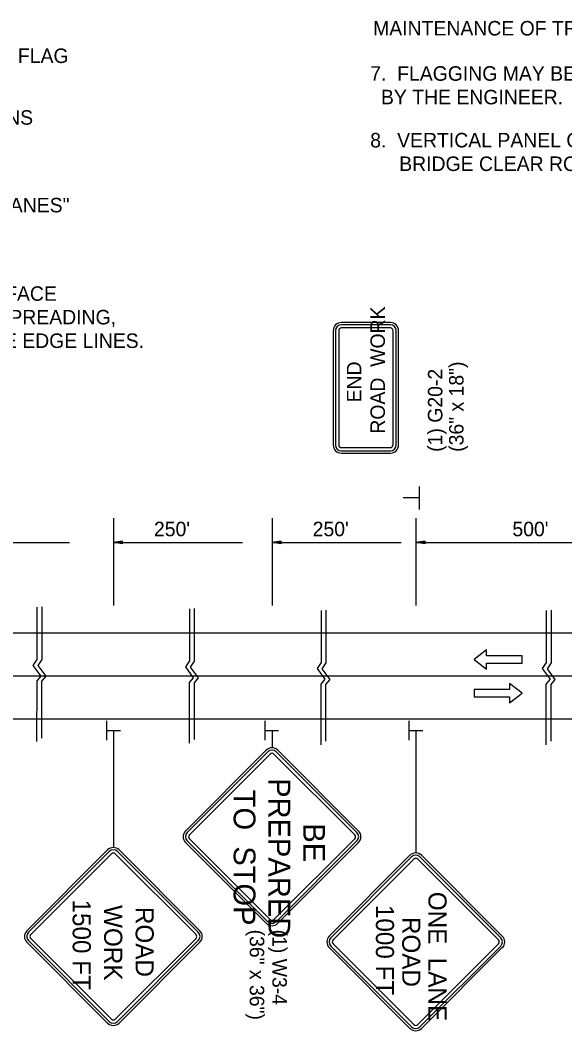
# Model space of a CAD drawing. Extents: x 1926586 to 1930787, y 596452 to 599566.
# Drawn here: x 1928209.4 to 1928434.7, y 597274.9 to 597692.9 of the extents above; entities that cross this region are included whole.
import ezdxf

# ---------------------------------------------------------------- set-up
doc = ezdxf.new("R2010")
doc.units = 0
for name, color, linetype in [('Default', 7, 'Continuous'), ('P_TC_Signs_Permanent', 7, 'Continuous'), ('P_TC_Signs_Temporary', 7, 'Continuous'), ('R_Border', 7, 'Continuous'), ('R_Striping', 7, 'Continuous')]:
    doc.layers.add(name, color=color, linetype=linetype)

msp = doc.modelspace()

# ---------------------------------------------------------------- linework, layer by layer
at = {"layer": 'Default'}
for p, q in [((1928374.44, 597500.09), (1928374.44, 597490.6)), ((1928374.3, 597495.36), (1928367.82, 597495.36)), ((1928247.97, 597486.95), (1928247.97, 597450.92)), ((1928313.63, 597486.95), (1928313.63, 597450.92)), ((1928373.08, 597486.95), (1928373.08, 597450.92)), ((1928176.38, 597476.91), (1928229.78, 597476.93)), ((1928251.81, 597477.5), (1928247.97, 597476.93)), ((1928247.97, 597476.93), (1928301.38, 597476.93)), ((1928251.81, 597476.35), (1928247.97, 597476.93)), ((1928251.81, 597477.41), (1928248.62, 597476.93)), ((1928251.81, 597476.45), (1928248.62, 597476.93)), ((1928251.81, 597477.31), (1928249.28, 597476.93)), ((1928251.81, 597476.55), (1928249.28, 597476.93)), ((1928251.81, 597477.21), (1928249.91, 597476.93)), ((1928251.81, 597476.64), (1928249.91, 597476.93)), ((1928251.81, 597477.12), (1928250.56, 597476.93)), ((1928251.81, 597476.74), (1928250.56, 597476.93)), ((1928251.81, 597477.02), (1928251.21, 597476.93)), ((1928251.81, 597476.84), (1928251.21, 597476.93)), ((1928251.81, 597476.35), (1928251.81, 597477.5)), ((1928317.46, 597477.48), (1928313.63, 597476.91)), ((1928313.63, 597476.91), (1928367.03, 597476.91)), ((1928317.46, 597476.33), (1928313.63, 597476.91)), ((1928317.46, 597477.39), (1928314.27, 597476.91)), ((1928317.46, 597476.43), (1928314.27, 597476.91)), ((1928317.46, 597477.29), (1928314.93, 597476.91)), ((1928317.46, 597476.53), (1928314.93, 597476.91)), ((1928317.46, 597477.19), (1928315.57, 597476.91)), ((1928317.46, 597476.62), (1928315.57, 597476.91)), ((1928317.46, 597477.1), (1928316.22, 597476.91)), ((1928317.46, 597476.72), (1928316.22, 597476.91)), ((1928317.46, 597477), (1928316.86, 597476.91)), ((1928317.46, 597476.82), (1928316.86, 597476.91)), ((1928317.46, 597476.33), (1928317.46, 597477.48)), ((1928376.92, 597477.48), (1928373.08, 597476.91)), ((1928373.08, 597476.91), (1928472.84, 597476.91)), ((1928376.92, 597476.33), (1928373.08, 597476.91)), ((1928376.92, 597477.39), (1928373.72, 597476.91)), ((1928376.92, 597476.43), (1928373.72, 597476.91)), ((1928376.92, 597477.29), (1928374.38, 597476.91)), ((1928376.92, 597476.53), (1928374.38, 597476.91)), ((1928376.92, 597477.19), (1928375.02, 597476.91)), ((1928376.92, 597476.62), (1928375.02, 597476.91)), ((1928376.92, 597477.1), (1928375.67, 597476.91)), ((1928376.92, 597476.72), (1928375.67, 597476.91)), ((1928376.92, 597477), (1928376.31, 597476.91)), ((1928376.92, 597476.82), (1928376.31, 597476.91)), ((1928376.92, 597476.33), (1928376.92, 597477.48)), ((1927870.1, 597439.49), (1929142.12, 597439.49)), ((1927870.1, 597421.7), (1929142.12, 597421.7)), ((1927870.1, 597403.91), (1929142.12, 597403.91)), ((1928245.3, 597395.11), (1928245.3, 597403.12)), ((1928310.78, 597395.11), (1928310.78, 597403.12)), ((1928370.4, 597395.11), (1928370.4, 597403.12)), ((1928245.42, 597399.09), (1928250.88, 597399.09)), ((1928310.9, 597399.09), (1928316.36, 597399.09)), ((1928370.52, 597399.09), (1928375.99, 597399.09))]:
    msp.add_line(p, q, dxfattribs=at)
for points in [[(1928216.38, 597450.1), (1928216.38, 597428.57), (1928214.72, 597426.1), (1928217.96, 597421.67), (1928216.26, 597419.63), (1928216.25, 597394.6)], [(1928218.43, 597450.29), (1928218.43, 597428.49), (1928216.77, 597426.02), (1928220, 597421.59), (1928218.3, 597419.54), (1928218.3, 597396.04)], [(1928279.43, 597449.42), (1928279.43, 597427.9), (1928277.76, 597425.43), (1928281, 597421), (1928279.3, 597418.96), (1928279.29, 597393.93)], [(1928281.47, 597449.62), (1928281.47, 597427.82), (1928279.81, 597425.34), (1928283.05, 597420.92), (1928281.34, 597418.87), (1928281.34, 597395.37)], [(1928333.89, 597448.78), (1928333.89, 597427.26), (1928332.23, 597424.79), (1928335.46, 597420.36), (1928333.76, 597418.31), (1928333.75, 597393.28)], [(1928335.93, 597448.97), (1928335.93, 597427.17), (1928334.27, 597424.7), (1928337.51, 597420.27), (1928335.8, 597418.22), (1928335.8, 597394.72)], [(1928427.05, 597448.78), (1928427.05, 597427.26), (1928425.39, 597424.79), (1928428.63, 597420.36), (1928426.92, 597418.31), (1928426.92, 597393.28)], [(1928429.1, 597448.97), (1928429.1, 597427.17), (1928427.43, 597424.7), (1928430.67, 597420.27), (1928428.97, 597418.22), (1928428.96, 597394.72)]]:
    msp.add_lwpolyline(points, dxfattribs=at)
at = {"layer": 'P_TC_Signs_Permanent'}
for p, q in [((1928311.24, 597391), (1928277.83, 597357.58)), ((1928311.9, 597390.33), (1928278.49, 597356.92)), ((1928312.83, 597389.4), (1928279.42, 597355.99)), ((1928347.83, 597355.99), (1928314.42, 597389.4)), ((1928348.76, 597356.92), (1928315.35, 597390.33)), ((1928349.42, 597357.58), (1928316.01, 597391)), ((1928277.83, 597352.81), (1928311.24, 597319.4)), ((1928278.49, 597353.47), (1928311.9, 597320.06)), ((1928279.42, 597354.4), (1928312.83, 597320.99)), ((1928314.42, 597320.99), (1928347.83, 597354.4)), ((1928315.35, 597320.06), (1928348.76, 597353.47)), ((1928316.01, 597319.4), (1928349.42, 597352.81))]:
    msp.add_line(p, q, dxfattribs=at)
for centre, radius, start, end in [((1928313.63, 597388.61), 3.37, 45, 135), ((1928313.63, 597388.61), 2.44, 45, 135), ((1928313.63, 597388.61), 1.13, 45, 135), ((1928280.22, 597355.2), 3.37, 135, 225), ((1928280.22, 597355.2), 2.44, 135, 225), ((1928280.22, 597355.2), 1.13, 135, 225), ((1928347.04, 597355.2), 1.13, 315, 45), ((1928347.04, 597355.2), 2.44, 315, 45), ((1928347.04, 597355.2), 3.37, 315, 45), ((1928313.63, 597321.79), 3.37, 225, 315), ((1928313.63, 597321.79), 2.44, 225, 315), ((1928313.63, 597321.79), 1.13, 225, 315)]:
    msp.add_arc(centre, radius, start, end, dxfattribs=at)
at = {"layer": 'P_TC_Signs_Temporary'}
for p, q in [((1928338.95, 597564.52), (1928338.95, 597517.27)), ((1928339.88, 597564.52), (1928339.88, 597517.27)), ((1928341.2, 597564.52), (1928341.2, 597517.27)), ((1928362.57, 597567.89), (1928342.32, 597567.89)), ((1928362.57, 597566.96), (1928342.32, 597566.96)), ((1928362.57, 597565.64), (1928342.32, 597565.64)), ((1928363.7, 597517.27), (1928363.7, 597564.52)), ((1928365.01, 597517.27), (1928365.01, 597564.52)), ((1928365.95, 597517.27), (1928365.95, 597564.52)), ((1928342.32, 597516.14), (1928362.57, 597516.14)), ((1928342.32, 597514.83), (1928362.57, 597514.83)), ((1928342.32, 597513.89), (1928362.57, 597513.89)), ((1928212.18, 597316.34), (1928245.59, 597349.75)), ((1928212.84, 597315.68), (1928246.25, 597349.09)), ((1928213.77, 597314.75), (1928247.18, 597348.16)), ((1928248.77, 597348.16), (1928282.18, 597314.75)), ((1928249.7, 597349.09), (1928283.11, 597315.68)), ((1928250.36, 597349.75), (1928283.77, 597316.34)), ((1928337.28, 597314.12), (1928370.69, 597347.53)), ((1928337.95, 597313.45), (1928371.36, 597346.86)), ((1928374.8, 597346.86), (1928408.22, 597313.45)), ((1928375.47, 597347.53), (1928408.88, 597314.12)), ((1928338.87, 597312.53), (1928372.29, 597345.94)), ((1928373.88, 597345.94), (1928407.29, 597312.53)), ((1928245.59, 597278.16), (1928212.18, 597311.57)), ((1928246.25, 597278.82), (1928212.84, 597312.23)), ((1928247.18, 597279.75), (1928213.77, 597313.16)), ((1928282.18, 597313.16), (1928248.77, 597279.75)), ((1928283.11, 597312.23), (1928249.7, 597278.82)), ((1928283.77, 597311.57), (1928250.36, 597278.16)), ((1928370.69, 597275.93), (1928337.28, 597309.34)), ((1928371.36, 597276.6), (1928337.95, 597310.01)), ((1928372.29, 597277.52), (1928338.87, 597310.94)), ((1928407.29, 597310.94), (1928373.88, 597277.52)), ((1928408.22, 597310.01), (1928374.8, 597276.6)), ((1928408.88, 597309.34), (1928375.47, 597275.93))]:
    msp.add_line(p, q, dxfattribs=at)
for centre, radius, start, end in [((1928342.32, 597564.52), 3.37, 90, 180), ((1928342.32, 597564.52), 2.44, 90, 180), ((1928342.32, 597564.52), 1.13, 90, 180), ((1928362.57, 597564.52), 3.37, 360, 90), ((1928362.57, 597564.52), 2.44, 360, 90), ((1928362.57, 597564.52), 1.13, 360, 90), ((1928342.32, 597517.27), 3.37, 180, 270), ((1928342.32, 597517.27), 2.44, 180, 270), ((1928342.32, 597517.27), 1.13, 180, 270), ((1928362.57, 597517.27), 2.44, 270, 360), ((1928362.57, 597517.27), 1.13, 270, 360), ((1928362.57, 597517.27), 3.37, 270, 360), ((1928247.97, 597347.36), 3.37, 45, 135), ((1928247.97, 597347.36), 2.44, 45, 135), ((1928247.97, 597347.36), 1.12, 45, 135), ((1928373.08, 597345.14), 3.37, 45, 135), ((1928373.08, 597345.14), 2.44, 45, 135), ((1928373.08, 597345.14), 1.12, 45, 135), ((1928214.56, 597313.95), 3.37, 135, 225), ((1928214.56, 597313.95), 2.44, 135, 225), ((1928214.56, 597313.95), 1.13, 135, 225), ((1928281.39, 597313.95), 1.13, 315, 45), ((1928281.39, 597313.95), 2.44, 315, 45), ((1928281.39, 597313.95), 3.37, 315, 45), ((1928339.67, 597311.73), 3.37, 135, 225), ((1928339.67, 597311.73), 2.44, 135, 225), ((1928406.49, 597311.73), 2.44, 315, 45), ((1928406.49, 597311.73), 3.37, 315, 45), ((1928339.67, 597311.73), 1.13, 135, 225), ((1928406.49, 597311.73), 1.13, 315, 45), ((1928247.97, 597280.54), 3.37, 225, 315), ((1928247.97, 597280.54), 2.44, 225, 315), ((1928247.97, 597280.54), 1.12, 225, 315), ((1928373.08, 597278.32), 3.37, 225, 315), ((1928373.08, 597278.32), 2.44, 225, 315), ((1928373.08, 597278.32), 1.12, 225, 315)]:
    msp.add_arc(centre, radius, start, end, dxfattribs=at)
at = {"layer": 'R_Border'}
for p, q in [((1928247.97, 597399.09), (1928247.97, 597350.74)), ((1928313.63, 597399.09), (1928313.63, 597391.98)), ((1928373.08, 597399.09), (1928373.08, 597348.52))]:
    msp.add_line(p, q, dxfattribs=at)
at = {"layer": 'R_Striping'}
for points in [[(1928402.37, 597432.54), (1928397.18, 597428.54), (1928402.37, 597424.54), (1928402.37, 597427.04), (1928417.08, 597427.04), (1928417.08, 597430.04), (1928402.37, 597430.04)], [(1928411.89, 597410.6), (1928417.08, 597414.6), (1928411.89, 597418.6), (1928411.89, 597416.1), (1928397.18, 597416.1), (1928397.18, 597413.1), (1928411.89, 597413.1)]]:
    msp.add_lwpolyline(points, close=True, dxfattribs=at)

# ---------------------------------------------------------------- texts
at = {"layer": 'Default'}
for s, p in [("250'", (1928264.78, 597479.5)), ("250'", (1928330.43, 597479.5)), ("500'", (1928413.06, 597479.5))]:
    msp.add_text(s, height=6, rotation=360, dxfattribs=at).set_placement(p)
at = {"layer": 'P_TC_Signs_Temporary'}
for s, height, rotation, p in [('ROAD  WORK', 6, 90, (1928360.32, 597521.93)), ('END', 6, 90, (1928350.57, 597534.86)), ('PREPARED', 9, 270, (1928312.15, 597379.44)), ('TO  STOP', 9, 270, (1928297.75, 597374.66)), ('BE', 9, 270, (1928326.55, 597360.75)), ('ONE  LANE', 7.5, 270, (1928378.33, 597332.43)), ('1500 FT', 7.5, 270, (1928231.14, 597329.24)), ('WORK', 7.5, 270, (1928244.16, 597326.94)), ('1000 FT', 7.5, 270, (1928356.58, 597327.02)), (' ROAD ', 7.5, 270, (1928257.19, 597328.97)), ('ROAD', 7.5, 270, (1928367.46, 597322.04))]:
    msp.add_text(s, height=height, rotation=rotation, dxfattribs=at).set_placement(p)
at = {"layer": 'R_Border'}
for s, height, rotation, p in [('MAINTENANCE OF TRAFFIC NOTES (CONT.) :', 6, 360, (1928355.43, 597686.62)), ('1.  THE CONTRACTOR SHALL PROVIDE 2-WAY RADIO COMMUNICATION FOR FLAG ', 6, 360, (1927908.03, 597675.24)), ('7.  FLAGGING MAY BE USED IF AND WHERE DIRECTED', 6, 360, (1928354.23, 597667.9)), ('  BY THE ENGINEER.', 6, 360, (1928354.23, 597658.15)), ('2.  THE CONTRACTOR SHALL FURNISH AND MAINTAIN STD. W8-1 "BUMP" SIGNS', 6, 360, (1927903.26, 597649.72)), ('8.  VERTICAL PANEL QUANTITIES ARE PROVIDED FOR', 6, 360, (1928354.23, 597640.32)), ('BRIDGE CLEAR ROADWAY WIDTH OF 28\'-0" OR LESS.', 6, 360, (1928366.23, 597630.57)), ('3.  THE CONTRACTOR SHALL FURNISH AND MAINTAIN STD. W8-11 "UNEVEN LANES" ', 6, 360, (1927902.27, 597613.46)), ('4.  THE EDGE LINES SHALL NOT BE PLACED ON THE FINISHED ASPHALT SURFACE', 6, 360, (1927901.36, 597576.87)), ('  UNTIL AFTER ALL WORK ADJACENT TO THE PAVEMENT EDGE, INCLUDING SPREADING,', 6, 360, (1927901.36, 597567.12)), ('  COMPACTING AND ETC. IS COMPLETED IN ORDER TO AVOID DAMAGING THE EDGE LINES.', 6, 360, (1927901.36, 597557.37)), ('(1) G20-2', 6, 90, (1928384.1, 597514.41)), ('(36" x 18")', 5.9996, 90, (1928392.85, 597514.41)), ('(36" x 36")', 5.9996, 270, (1928304.39, 597316.8)), ('(1) W3-4', 6, 270, (1928313.76, 597316.8))]:
    msp.add_text(s, height=height, rotation=rotation, dxfattribs=at).set_placement(p)

doc.saveas('drawing.dxf')
